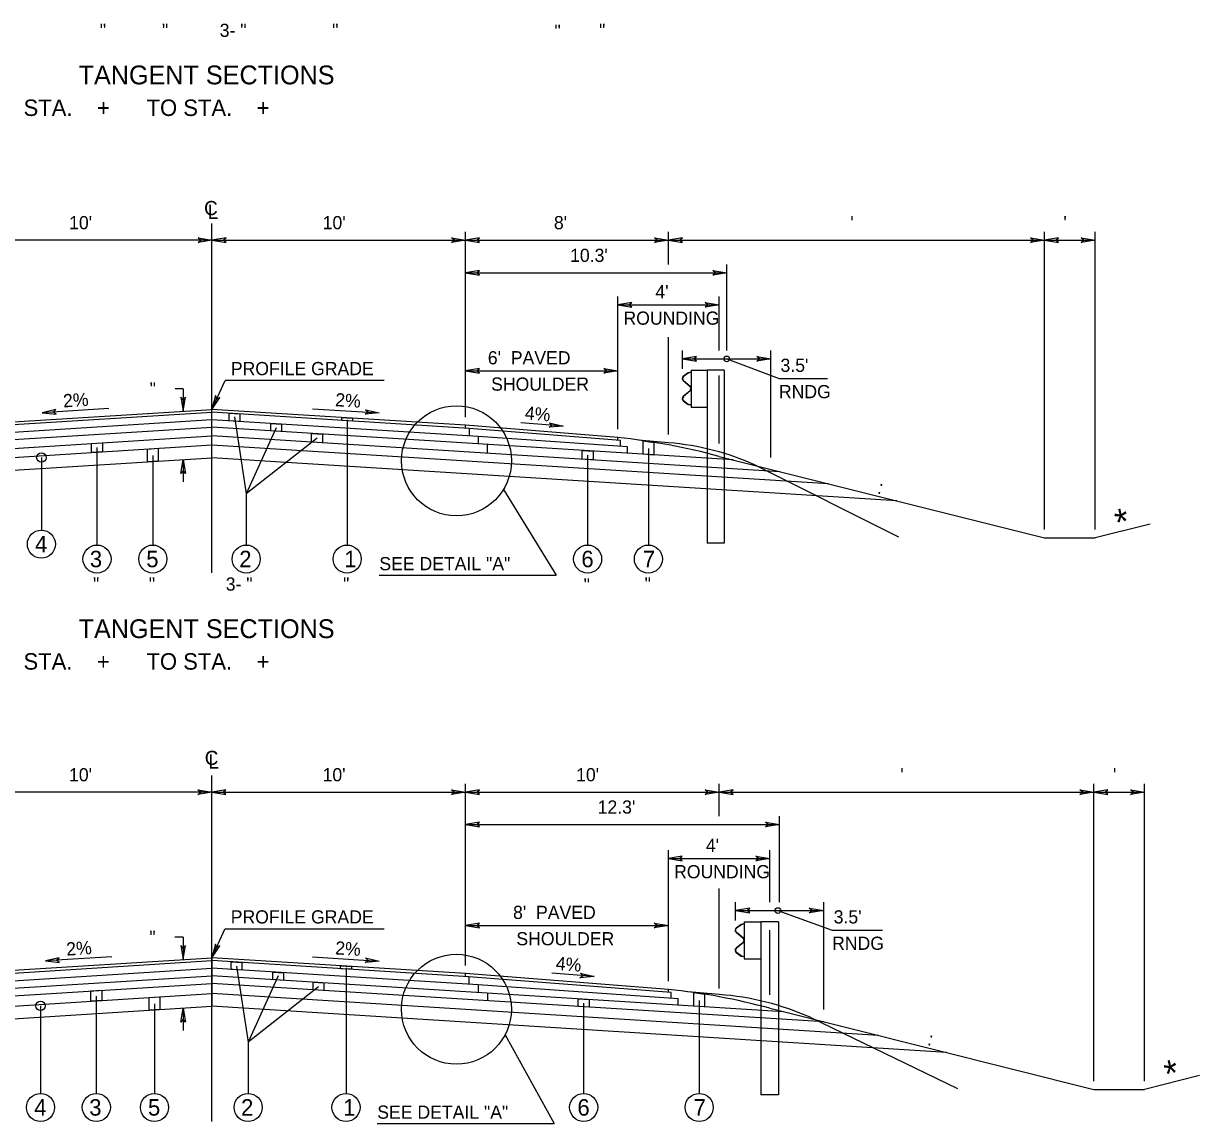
# Model space of a CAD drawing. Extents: x -592 to 1199, y -590 to 416.
# Drawn here: x -350.2 to -225.3, y -321.2 to -204.3 of the extents above; entities that cross this region are included whole.
import ezdxf

# ---------------------------------------------------------------- set-up
doc = ezdxf.new("R2010")
doc.units = 0
doc.layers.add('1', color=7, linetype='Continuous')
doc.layers.add('Des_ Drain_ Ftrs', color=7, linetype='Continuous')

msp = doc.modelspace()

# ---------------------------------------------------------------- linework, layer by layer
at = {"layer": '1'}
for p, q in [((-330.22, -262.69), (-330.22, -225.57)), ((-330.22, -227.33), (-357.16, -227.33)), ((-330.22, -227.33), (-303.27, -227.33)), ((-303.27, -246.13), (-303.27, -226.45)), ((-303.27, -227.33), (-281.72, -227.33)), ((-281.72, -229.92), (-281.72, -226.45)), ((-281.72, -227.33), (-241.76, -227.33)), ((-241.76, -258.08), (-241.76, -226.45)), ((-241.76, -227.33), (-236.38, -227.33)), ((-236.38, -258.08), (-236.38, -226.45)), ((-303.28, -230.8), (-275.53, -230.8)), ((-275.53, -239.07), (-275.53, -229.92)), ((-287.11, -247.43), (-287.11, -233.34)), ((-276.33, -239.07), (-276.33, -233.34)), ((-287.11, -234.22), (-276.33, -234.22)), ((-281.72, -247.98), (-281.72, -237.63)), ((-280.22, -241.02), (-280.22, -239.07)), ((-270.84, -250.44), (-270.84, -239.07)), ((-280.22, -239.95), (-270.84, -239.95)), ((-279.31, -241.14), (-279.31, -245.07)), ((-279.31, -241.14), (-277.62, -241.14)), ((-277.62, -241.14), (-277.62, -259.53)), ((-275.8, -241.14), (-277.62, -241.14)), ((-275.8, -241.14), (-275.8, -259.53)), ((-275.53, -239.95), (-269.97, -242.02)), ((-330.22, -245.31), (-328.83, -242.26)), ((-311.91, -242.26), (-328.83, -242.26)), ((-303.27, -241.23), (-287.11, -241.23)), ((-280.15, -242.24), (-279.42, -242.88)), ((-279.62, -241.42), (-280.14, -241.81)), ((-280.14, -242.22), (-279.4, -242.86)), ((-279.61, -241.45), (-280.12, -241.83)), ((-279.31, -241.37), (-279.62, -241.42)), ((-279.31, -241.4), (-279.61, -241.45)), ((-276.33, -248.95), (-276.33, -241.71)), ((-269.97, -242.02), (-264.82, -242.02)), ((-333.27, -243.13), (-334.15, -243.13)), ((-333.27, -243.13), (-333.27, -245.5)), ((-279.42, -243.33), (-280.15, -243.96)), ((-279.4, -243.35), (-280.14, -243.99)), ((-279.34, -243.07), (-279.34, -243.14)), ((-279.31, -243.07), (-279.31, -243.14)), ((-280.14, -244.4), (-279.62, -244.79)), ((-280.12, -244.37), (-279.61, -244.76)), ((-279.62, -244.79), (-279.31, -244.84)), ((-279.61, -244.76), (-279.31, -244.81)), ((-357.52, -247.32), (-330.22, -245.61)), ((-357.16, -247), (-330.22, -245.31)), ((-341.19, -245.23), (-348.27, -245.67)), ((-303.27, -247), (-330.22, -245.31)), ((-302.91, -247.33), (-330.22, -245.61)), ((-327.82, -246.12), (-326.58, -254.27)), ((-319.53, -245.24), (-312.45, -245.69)), ((-279.31, -245.07), (-277.62, -245.07)), ((-385.56, -250.68), (-330.22, -247.2)), ((-358.49, -248.18), (-330.22, -246.4)), ((-301.94, -248.19), (-330.22, -246.41)), ((-274.86, -250.69), (-330.22, -247.2)), ((-323.4, -247.26), (-326.58, -254.27)), ((-315.86, -246.41), (-315.86, -259.72)), ((-287.11, -248.31), (-303.27, -247)), ((-303.27, -247.3), (-303.27, -247)), ((-286.81, -248.63), (-302.91, -247.33)), ((-302.91, -247.33), (-302.91, -248.11)), ((-292.91, -247.09), (-297.39, -246.73)), ((-390.53, -251.92), (-330.22, -248.13)), ((-269.9, -251.93), (-330.22, -248.13)), ((-319.06, -248.38), (-326.58, -254.27)), ((-301.94, -248.19), (-301.94, -248.98)), ((-286.07, -249.3), (-301.94, -248.19)), ((-287.11, -248.61), (-287.11, -248.31)), ((-286.81, -249.24), (-286.81, -248.63)), ((-395.7, -253.21), (-330.22, -249.09)), ((-342.44, -249.37), (-342.44, -259.72)), ((-264.73, -253.22), (-330.22, -249.1)), ((-300.97, -249.04), (-300.97, -249.97)), ((-286.07, -249.98), (-286.07, -249.3)), ((-283.85, -249.46), (-283.85, -259.72)), ((-280.22, -249.08), (-280.22, -249.08)), ((-402.99, -255.03), (-330.22, -250.46)), ((-348.35, -250.43), (-348.35, -258.14)), ((-336.51, -250.2), (-336.51, -259.72)), ((-333.27, -250.66), (-333.27, -253.02)), ((-257.45, -255.04), (-330.22, -250.46)), ((-290.31, -250.19), (-290.31, -259.72)), ((-276.33, -250.32), (-241.76, -258.96)), ((-272.34, -251.32), (-257.29, -258.84)), ((-326.58, -254.27), (-326.58, -259.72)), ((-299.26, -253.83), (-293.66, -262.91)), ((-230.55, -257.5), (-236.38, -258.96)), ((-275.8, -259.53), (-277.62, -259.53)), ((-241.76, -258.96), (-236.38, -258.96)), ((-312.45, -262.91), (-293.66, -262.91)), ((-330.23, -320.94), (-330.23, -284.21)), ((-330.23, -285.97), (-357.17, -285.97)), ((-330.23, -285.97), (-303.29, -285.97)), ((-303.29, -304.37), (-303.29, -285.09)), ((-303.29, -285.97), (-276.34, -285.97)), ((-276.34, -288.52), (-276.34, -285.09)), ((-276.34, -285.97), (-236.51, -285.97)), ((-236.51, -316.66), (-236.51, -285.09)), ((-236.51, -285.97), (-231.12, -285.97)), ((-231.12, -316.66), (-231.12, -285.09)), ((-269.91, -297.67), (-269.91, -288.52)), ((-303.28, -289.4), (-269.91, -289.4)), ((-281.73, -306.04), (-281.73, -292.14)), ((-270.96, -297.67), (-270.96, -292.14)), ((-281.73, -293.02), (-270.96, -293.02)), ((-276.34, -306.82), (-276.34, -296.19)), ((-274.61, -299.62), (-274.61, -297.67)), ((-274.61, -298.55), (-265.22, -298.55)), ((-270.09, -298.55), (-264.32, -300.62)), ((-265.22, -309.04), (-265.22, -297.67)), ((-273.66, -299.74), (-273.66, -303.67)), ((-273.66, -299.74), (-271.91, -299.74)), ((-271.91, -299.74), (-271.91, -318.13)), ((-270.02, -299.74), (-271.91, -299.74)), ((-270.02, -299.74), (-270.02, -318.13)), ((-330.23, -303.56), (-328.84, -300.51)), ((-311.92, -300.51), (-328.84, -300.51)), ((-303.29, -300.14), (-281.73, -300.14)), ((-274.54, -300.84), (-273.78, -301.48)), ((-273.99, -300.02), (-274.52, -300.41)), ((-274.52, -300.82), (-273.76, -301.46)), ((-273.97, -300.05), (-274.5, -300.43)), ((-273.66, -299.97), (-273.99, -300.02)), ((-273.66, -300), (-273.97, -300.05)), ((-270.96, -307.49), (-270.96, -300.62)), ((-264.32, -300.62), (-258.98, -300.62)), ((-333.3, -301.38), (-334.18, -301.38)), ((-333.3, -301.38), (-333.3, -303.75)), ((-273.78, -301.93), (-274.54, -302.56)), ((-273.76, -301.95), (-274.52, -302.59)), ((-273.69, -301.67), (-273.69, -301.74)), ((-273.66, -301.67), (-273.66, -301.74)), ((-357.17, -305.25), (-330.23, -303.56)), ((-340.85, -303.46), (-347.92, -303.9)), ((-330.23, -303.56), (-330.23, -303.86)), ((-303.29, -305.25), (-330.23, -303.56)), ((-319.53, -303.48), (-312.45, -303.92)), ((-274.52, -303), (-273.99, -303.39)), ((-274.5, -302.97), (-273.97, -303.36)), ((-273.99, -303.39), (-273.66, -303.44)), ((-273.97, -303.36), (-273.66, -303.41)), ((-358.53, -306.45), (-330.23, -304.67)), ((-357.54, -305.58), (-330.23, -303.86)), ((-330.23, -303.86), (-330.23, -304.67)), ((-302.92, -305.58), (-330.23, -303.86)), ((-330.23, -304.67), (-330.23, -305.48)), ((-301.93, -306.45), (-330.23, -304.67)), ((-327.62, -304.44), (-326.38, -312.52)), ((-315.98, -304.64), (-315.98, -317.97)), ((-273.66, -303.67), (-271.91, -303.67)), ((-390.95, -309.29), (-330.23, -305.48)), ((-330.23, -305.48), (-330.23, -306.29)), ((-269.49, -309.3), (-330.23, -305.48)), ((-323.18, -305.47), (-326.38, -312.52)), ((-281.73, -306.92), (-303.29, -305.25)), ((-303.29, -305.55), (-303.29, -305.25)), ((-302.92, -305.58), (-302.92, -306.39)), ((-281.43, -307.25), (-302.92, -305.58)), ((-289.62, -305.55), (-294.1, -305.2)), ((-401.04, -311.82), (-330.23, -307.37)), ((-395.27, -310.37), (-330.23, -306.29)), ((-330.23, -306.29), (-330.23, -307.37)), ((-265.17, -310.38), (-330.23, -306.29)), ((-330.23, -307.37), (-330.23, -308.71)), ((-259.4, -311.82), (-330.23, -307.37)), ((-318.9, -306.66), (-326.38, -312.52)), ((-301.93, -306.45), (-301.93, -307.26)), ((-280.7, -307.91), (-301.93, -306.45)), ((-300.94, -307.32), (-300.94, -308.13)), ((-281.73, -307.22), (-281.73, -306.92)), ((-281.43, -307.86), (-281.43, -307.25)), ((-342.51, -307.63), (-342.51, -317.97)), ((-336.33, -308.47), (-336.33, -317.97)), ((-290.73, -308.38), (-290.73, -317.97)), ((-280.7, -308.59), (-280.7, -307.91)), ((-278.45, -308.1), (-278.45, -317.97)), ((-274.61, -307.68), (-274.61, -307.68)), ((-408.24, -313.62), (-330.23, -308.71)), ((-348.44, -308.68), (-348.44, -317.97)), ((-333.3, -308.9), (-333.3, -311.27)), ((-252.19, -313.62), (-330.23, -308.71)), ((-270.96, -308.93), (-236.51, -317.54)), ((-266.6, -309.92), (-250.99, -317.44)), ((-299.08, -311.74), (-293.88, -321.16)), ((-326.38, -312.52), (-326.38, -317.97)), ((-225.29, -316.08), (-231.12, -317.54)), ((-270.02, -318.13), (-271.91, -318.13)), ((-236.51, -317.54), (-231.12, -317.54)), ((-312.67, -321.16), (-293.88, -321.16))]:
    msp.add_line(p, q, dxfattribs=at)
for points in [[(-328.39, -245.72), (-327.25, -245.8), (-327.25, -246.59), (-328.39, -246.52)], [(-323.97, -246.8), (-322.83, -246.87), (-322.83, -247.67), (-323.97, -247.6)], [(-316.44, -246.18), (-315.29, -246.25), (-315.29, -246.55), (-316.44, -246.48)], [(-319.63, -247.87), (-318.48, -247.94), (-318.48, -248.87), (-319.63, -248.8)], [(-284.42, -248.64), (-283.28, -248.82), (-283.28, -250.16), (-284.42, -250.08)], [(-343.01, -248.93), (-341.87, -248.86), (-341.87, -249.83), (-343.01, -249.9)], [(-337.08, -249.53), (-335.94, -249.45), (-335.94, -250.82), (-337.08, -250.89)], [(-290.88, -249.68), (-289.73, -249.75), (-289.73, -250.68), (-290.88, -250.61)], [(-328.19, -303.99), (-327.05, -304.06), (-327.05, -304.87), (-328.19, -304.8)], [(-316.55, -304.42), (-315.4, -304.49), (-315.4, -304.79), (-316.55, -304.72)], [(-323.76, -305.08), (-322.61, -305.15), (-322.61, -305.96), (-323.76, -305.88)], [(-343.08, -307.09), (-341.93, -307.02), (-341.93, -308.1), (-343.08, -308.17)], [(-319.47, -306.15), (-318.33, -306.23), (-318.33, -307.03), (-319.47, -306.96)], [(-279.03, -307.26), (-277.88, -307.43), (-277.88, -308.77), (-279.03, -308.7)], [(-336.9, -307.78), (-335.75, -307.71), (-335.75, -309.06), (-336.9, -309.13)], [(-291.3, -307.93), (-290.16, -308), (-290.16, -308.81), (-291.3, -308.73)]]:
    msp.add_lwpolyline(points, close=True, dxfattribs=at)
for centre, radius in [((-275.53, -239.95), 0.3), ((-304.24, -250.78), 5.84), ((-348.35, -250.43), 0.5), ((-348.35, -259.63), 1.49), ((-342.44, -261.21), 1.49), ((-336.51, -261.21), 1.49), ((-326.58, -261.21), 1.49), ((-315.86, -261.21), 1.49), ((-290.31, -261.21), 1.49), ((-283.85, -261.21), 1.49), ((-304.25, -309.03), 5.84), ((-348.44, -308.68), 0.5), ((-348.44, -319.46), 1.49), ((-342.51, -319.46), 1.49), ((-336.33, -319.46), 1.49), ((-326.38, -319.46), 1.49), ((-315.98, -319.46), 1.49), ((-290.73, -319.46), 1.49), ((-278.45, -319.46), 1.49)]:
    msp.add_circle(centre, radius, dxfattribs=at)
for centre, radius, start, end in [((-279.97, -242.03), 0.278, 126.9799, 229.021), ((-279.97, -242.03), 0.249, 126.9799, 229.021), ((-279.59, -243.07), 0.249, 0, 49.0365), ((-279.59, -243.14), 0.249, 310.9635, 0), ((-279.59, -243.07), 0.278, 0, 49.0365), ((-279.59, -243.14), 0.278, 310.9635, 0), ((-279.97, -244.17), 0.278, 130.979, 233.0201), ((-279.97, -244.17), 0.249, 130.979, 233.0201), ((-293.99, -315.14), 67.19, 74.7619, 84.1205), ((-292.54, -349.53), 101.24, 83.8633, 85.6775), ((-283.84, -276.15), 27.37, 65.1374, 85.5513), ((-288.62, -373.76), 67.19, 74.7598, 84.1183)]:
    msp.add_arc(centre, radius, start, end, dxfattribs=at)
msp.add_ellipse((-270.09, -298.55), major_axis=(-0.311, 0), ratio=0.964041, dxfattribs=at)
for centre, major_axis, start_param, end_param in [((-274.35, -300.63), (-0.288, 0), 5.35781, 7.138763), ((-274.35, -300.63), (-0.258, 0), 5.35781, 7.138763), ((-273.95, -301.67), (0.258, 0), 0, 0.855848), ((-273.95, -301.74), (0.258, 0), 5.427337, 6.283185), ((-273.95, -301.67), (0.288, 0), 0, 0.855848), ((-273.95, -301.74), (0.288, 0), 5.427337, 6.283185), ((-274.35, -302.77), (-0.288, 0), 5.427608, 7.208561), ((-274.35, -302.77), (-0.258, 0), 5.427608, 7.208561), ((-287.56, -408.13), (105.02, 0), 1.463691, 1.495354), ((-278.54, -334.75), (28.39, 0), 1.136862, 1.493152)]:
    msp.add_ellipse(centre, major_axis=major_axis, ratio=0.964041, start_param=start_param, end_param=end_param, dxfattribs=at)
at = {"layer": 'Des_ Drain_ Ftrs'}
for points in [[(-330.22, -227.33), (-331.7, -227.58), (-331.41, -227.33), (-331.7, -227.08)], [(-330.22, -227.33), (-328.73, -227.58), (-329.02, -227.33), (-328.73, -227.08)], [(-303.27, -227.33), (-304.76, -227.58), (-304.47, -227.33), (-304.76, -227.08)], [(-303.27, -227.33), (-301.79, -227.58), (-302.08, -227.33), (-301.79, -227.08)], [(-281.72, -227.33), (-283.21, -227.58), (-282.91, -227.33), (-283.21, -227.08)], [(-281.72, -227.33), (-280.23, -227.58), (-280.53, -227.33), (-280.23, -227.08)], [(-241.76, -227.33), (-243.25, -227.58), (-242.96, -227.33), (-243.25, -227.08)], [(-241.76, -227.33), (-240.28, -227.58), (-240.57, -227.33), (-240.28, -227.08)], [(-236.38, -227.33), (-237.86, -227.58), (-237.57, -227.33), (-237.86, -227.08)], [(-303.28, -230.8), (-301.79, -231.05), (-302.09, -230.8), (-301.79, -230.55)], [(-275.53, -230.8), (-277.02, -231.05), (-276.72, -230.8), (-277.02, -230.55)], [(-287.11, -234.22), (-285.62, -234.47), (-285.92, -234.22), (-285.62, -233.97)], [(-276.33, -234.22), (-277.82, -234.47), (-277.53, -234.22), (-277.82, -233.97)], [(-280.22, -239.95), (-278.73, -240.2), (-279.03, -239.95), (-278.73, -239.71)], [(-270.84, -239.95), (-272.32, -240.2), (-272.03, -239.95), (-272.32, -239.71)], [(-303.27, -241.23), (-301.79, -241.48), (-302.08, -241.23), (-301.79, -240.98)], [(-287.11, -241.23), (-288.6, -241.48), (-288.3, -241.23), (-288.6, -240.98)], [(-333.27, -245.5), (-333.02, -244.01), (-333.27, -244.31), (-333.52, -244.01)], [(-330.22, -245.31), (-329.37, -244.06), (-329.72, -244.22), (-329.83, -243.85)], [(-348.27, -245.67), (-346.77, -245.83), (-347.08, -245.6), (-346.8, -245.33)], [(-312.45, -245.69), (-313.95, -245.84), (-313.64, -245.61), (-313.92, -245.35)], [(-292.91, -247.09), (-294.41, -247.22), (-294.1, -247), (-294.37, -246.73)], [(-333.27, -250.66), (-333.02, -252.14), (-333.27, -251.85), (-333.52, -252.14)], [(-330.23, -285.97), (-331.72, -286.22), (-331.42, -285.97), (-331.72, -285.72)], [(-330.23, -285.97), (-328.74, -286.22), (-329.03, -285.97), (-328.74, -285.72)], [(-303.29, -285.97), (-304.77, -286.22), (-304.48, -285.97), (-304.77, -285.72)], [(-303.29, -285.97), (-301.8, -286.22), (-302.09, -285.97), (-301.8, -285.72)], [(-276.34, -285.97), (-277.83, -286.22), (-277.54, -285.97), (-277.83, -285.72)], [(-276.34, -285.97), (-274.86, -286.22), (-275.15, -285.97), (-274.86, -285.72)], [(-236.51, -285.97), (-238, -286.22), (-237.7, -285.97), (-238, -285.72)], [(-236.51, -285.97), (-235.02, -286.22), (-235.32, -285.97), (-235.02, -285.72)], [(-231.12, -285.97), (-232.61, -286.22), (-232.32, -285.97), (-232.61, -285.72)], [(-303.28, -289.4), (-301.79, -289.65), (-302.09, -289.4), (-301.79, -289.15)], [(-269.91, -289.4), (-271.4, -289.65), (-271.11, -289.4), (-271.4, -289.15)], [(-281.73, -293.02), (-280.25, -293.27), (-280.54, -293.02), (-280.25, -292.77)], [(-270.96, -293.02), (-272.45, -293.27), (-272.15, -293.02), (-272.45, -292.77)], [(-274.61, -298.55), (-273.06, -298.8), (-273.37, -298.55), (-273.06, -298.3)], [(-265.22, -298.55), (-266.77, -298.8), (-266.46, -298.55), (-266.77, -298.3)], [(-303.29, -300.14), (-301.8, -300.39), (-302.09, -300.14), (-301.8, -299.89)], [(-281.73, -300.14), (-283.22, -300.39), (-282.93, -300.14), (-283.22, -299.89)], [(-333.3, -303.75), (-333.05, -302.26), (-333.3, -302.56), (-333.54, -302.26)], [(-330.23, -303.56), (-329.38, -302.31), (-329.73, -302.47), (-329.84, -302.1)], [(-347.92, -303.9), (-346.42, -304.06), (-346.73, -303.83), (-346.46, -303.56)], [(-312.45, -303.92), (-313.95, -304.08), (-313.64, -303.85), (-313.92, -303.58)], [(-289.62, -305.55), (-291.12, -305.68), (-290.81, -305.46), (-291.08, -305.19)], [(-333.3, -308.9), (-333.05, -310.39), (-333.3, -310.1), (-333.54, -310.39)]]:
    msp.add_lwpolyline(points, close=True, dxfattribs=at)

# ---------------------------------------------------------------- texts
at = {"layer": '1'}
for s, height, p in [(' "', 1.4, (-342.66, -205.75)), (' "', 1.4, (-336.05, -205.75)), ('3- "', 1.4, (-329.4, -205.75)), (' "', 1.4, (-317.97, -205.75)), (' "', 1.4, (-294.35, -205.85)), ('  "', 1.4, (-290.13, -205.75)), ('TANGENT SECTIONS', 2, (-344.39, -210.79)), ('STA.    +      TO STA.    +     ', 1.75, (-350.24, -214.15)), ("10'", 1.4, (-345.4, -226.18)), ("10'", 1.4, (-318.46, -226.18)), ("8'", 1.4, (-293.89, -226.18)), ("  '", 1.4, (-263.44, -226.18)), (" '", 1.4, (-240.27, -226.18)), ("10.3'", 1.4, (-292.17, -229.65)), ("4'", 1.4, (-283.11, -233.52)), ('ROUNDING', 1.4, (-286.5, -236.32)), ("6'  PAVED", 1.4, (-300.91, -240.53)), ("3.5'", 1.4, (-269.81, -241.33)), ('PROFILE GRADE', 1.4, (-328.22, -241.68)), ('SHOULDER', 1.4, (-300.56, -243.33)), ('RNDG', 1.4, (-269.98, -244.13)), ('4', 1.75, (-349.02, -260.5)), ('3', 1.75, (-343.2, -262.08)), ('5', 1.75, (-337.2, -262.08)), ('2', 1.75, (-327.32, -262.08)), ('1', 1.75, (-316.16, -262.08)), ('SEE DETAIL "A"', 1.4, (-312.44, -262.4)), ('6', 1.75, (-290.97, -262.08)), ('7', 1.75, (-284.44, -262.08)), (' "', 1.4, (-343.38, -264.57)), (' "', 1.4, (-337.45, -264.57)), ('3- "', 1.4, (-328.76, -264.57)), (' "', 1.4, (-316.81, -264.57)), (' "', 1.4, (-291.25, -264.66)), ('  "', 1.4, (-285.29, -264.57)), ('TANGENT SECTIONS', 2, (-344.39, -269.61)), ('STA.    +      TO STA.    +     ', 1.75, (-350.25, -272.96)), ("10'", 1.4, (-345.41, -284.82)), ("10'", 1.4, (-318.47, -284.82)), ("10'", 1.4, (-291.53, -284.82)), ("  '", 1.4, (-258.12, -284.82)), (" '", 1.4, (-235.01, -284.82)), ("12.3'", 1.4, (-289.24, -288.25)), ("4'", 1.4, (-277.74, -292.32)), ('ROUNDING', 1.4, (-281.12, -295.12)), ('PROFILE GRADE', 1.4, (-328.23, -299.92)), ("8'  PAVED", 1.4, (-298.23, -299.44)), ("3.5'", 1.4, (-264.16, -299.92)), ('SHOULDER', 1.4, (-297.88, -302.24)), ('RNDG', 1.4, (-264.33, -302.72)), ('4', 1.75, (-349.11, -320.33)), ('3', 1.75, (-343.26, -320.33)), ('5', 1.75, (-337.02, -320.33)), ('2', 1.75, (-327.13, -320.33)), ('1', 1.75, (-316.28, -320.33)), ('6', 1.75, (-291.39, -320.33)), ('7', 1.75, (-279.04, -320.33)), ('SEE DETAIL "A"', 1.4, (-312.66, -320.66))]:
    msp.add_text(s, height=height, dxfattribs=at).set_placement(p)
for s, height, rotation, p in [('2%', 1.4, 3.7235, (-346, -245.11)), ('  "', 1.4, 0.1438, (-337.88, -243.84)), ('2%', 1.4, 356.2763, (-317.16, -244.97)), ('4%', 1.4, 355.1224, (-297.02, -246.37)), (' : ', 1.4, 345.7718, (-260.1, -254.09)), ('*', 2.8, 12.8479, (-233.91, -258.77)), ('  "', 1.4, 0.1438, (-337.91, -302.09)), ('2%', 1.4, 3.7237, (-345.66, -303.34)), ('2%', 1.4, 356.2769, (-317.16, -303.2)), ('4%', 1.4, 355.2889, (-293.73, -304.83)), (' : ', 1.4, 345.7718, (-254.78, -312.68)), ('*', 2.8, 12.8479, (-228.66, -317.35))]:
    msp.add_text(s, height=height, rotation=rotation, dxfattribs=at).set_placement(p)
at = {"layer": 'Des_ Drain_ Ftrs'}
for s, p in [('C', (-331.06, -224.68)), ('L', (-330.67, -225.08)), ('C', (-330.99, -283.08)), ('L', (-330.59, -283.47))]:
    msp.add_text(s, height=1.5, dxfattribs=at).set_placement(p)

doc.saveas('drawing.dxf')
